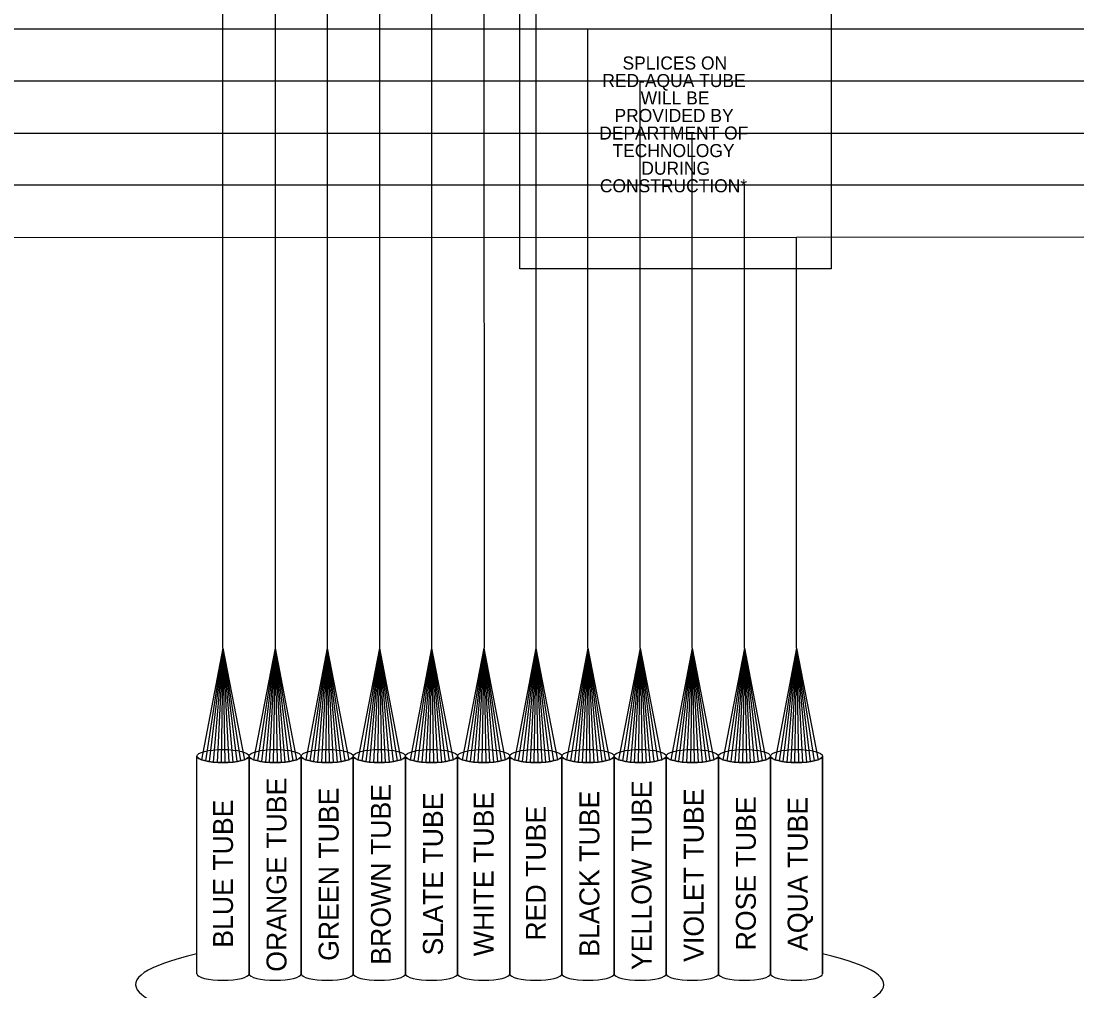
# Model space of a CAD drawing. Extents: x 1805893 to 1833564, y 708898 to 716199.
# Drawn here: x 1832449.4 to 1832571.6, y 713870.5 to 713982.1 of the extents above; entities that cross this region are included whole.
import ezdxf

# ---------------------------------------------------------------- set-up
doc = ezdxf.new("R2010")
doc.units = 0
doc.layers.add('SH_Data', color=7, linetype='Continuous')
doc.layers.add('SH_Text', color=7, linetype='Continuous')

msp = doc.modelspace()

# ---------------------------------------------------------------- linework, layer by layer
at = {"layer": 'SH_Data'}
for p, q in [((1832472.58, 713909.97), (1832472.58, 714031.78)), ((1832478.58, 714014.82), (1832478.58, 713909.97)), ((1832496.58, 714014.82), (1832496.58, 713909.97)), ((1832484.58, 714008.82), (1832484.58, 713909.97)), ((1832490.58, 714002.82), (1832490.58, 713909.97)), ((1832502.58, 714002.82), (1832502.62, 713909.97)), ((1832508.58, 713987.23), (1832508.58, 713909.97)), ((1832424.05, 713981.23), (1832514.58, 713981.23)), ((1832514.58, 713981.23), (1832571.62, 713981.23)), ((1832514.58, 713909.97), (1832514.58, 713981.23)), ((1832424.05, 713975.23), (1832520.58, 713975.23)), ((1832520.58, 713975.23), (1832571.62, 713975.23)), ((1832520.58, 713909.97), (1832520.58, 713975.23)), ((1832424.05, 713969.23), (1832526.58, 713969.23)), ((1832526.58, 713969.23), (1832571.62, 713969.23)), ((1832526.58, 713909.97), (1832526.58, 713969.23)), ((1832532.59, 713963.23), (1832424.05, 713963.23)), ((1832532.58, 713909.97), (1832532.58, 713963.23)), ((1832571.62, 713963.23), (1832532.59, 713963.23)), ((1832538.58, 713957.23), (1832424.05, 713957.19)), ((1832538.57, 713909.97), (1832538.59, 713957.23)), ((1832571.62, 713957.24), (1832538.59, 713957.23)), ((1832472.58, 713909.97), (1832470.11, 713897.12)), ((1832472.58, 713909.97), (1832470.56, 713897)), ((1832472.58, 713909.97), (1832471.01, 713896.91)), ((1832472.58, 713909.97), (1832471.46, 713896.85)), ((1832472.58, 713909.97), (1832471.91, 713896.82)), ((1832472.58, 713909.97), (1832472.36, 713896.8)), ((1832472.58, 713909.97), (1832473.71, 713896.85)), ((1832472.58, 713909.97), (1832474.16, 713896.91)), ((1832472.58, 713909.97), (1832474.61, 713897)), ((1832472.58, 713909.97), (1832475.06, 713897.12)), ((1832472.58, 713909.97), (1832473.26, 713896.82)), ((1832472.58, 713909.97), (1832472.81, 713896.8)), ((1832478.58, 713909.97), (1832476.11, 713897.12)), ((1832478.58, 713909.97), (1832476.56, 713897)), ((1832478.58, 713909.97), (1832477.01, 713896.91)), ((1832478.58, 713909.97), (1832477.46, 713896.85)), ((1832478.58, 713909.97), (1832477.91, 713896.82)), ((1832478.58, 713909.97), (1832478.36, 713896.8)), ((1832478.58, 713909.97), (1832479.71, 713896.85)), ((1832478.58, 713909.97), (1832480.16, 713896.91)), ((1832478.58, 713909.97), (1832480.61, 713897)), ((1832478.58, 713909.97), (1832481.06, 713897.12)), ((1832478.58, 713909.97), (1832479.26, 713896.82)), ((1832478.58, 713909.97), (1832478.81, 713896.8)), ((1832484.58, 713909.97), (1832482.11, 713897.12)), ((1832484.58, 713909.97), (1832482.56, 713897)), ((1832484.58, 713909.97), (1832483.01, 713896.91)), ((1832484.58, 713909.97), (1832483.46, 713896.85)), ((1832484.58, 713909.97), (1832483.91, 713896.82)), ((1832484.58, 713909.97), (1832484.36, 713896.8)), ((1832484.58, 713909.97), (1832485.71, 713896.85)), ((1832484.58, 713909.97), (1832486.16, 713896.91)), ((1832484.58, 713909.97), (1832486.61, 713897)), ((1832484.58, 713909.97), (1832487.06, 713897.12)), ((1832484.58, 713909.97), (1832485.26, 713896.82)), ((1832484.58, 713909.97), (1832484.81, 713896.8)), ((1832490.58, 713909.97), (1832488.11, 713897.12)), ((1832490.58, 713909.97), (1832488.56, 713897)), ((1832490.58, 713909.97), (1832489.01, 713896.91)), ((1832490.58, 713909.97), (1832489.46, 713896.85)), ((1832490.58, 713909.97), (1832489.91, 713896.82)), ((1832490.58, 713909.97), (1832490.36, 713896.8)), ((1832490.58, 713909.97), (1832491.71, 713896.85)), ((1832490.58, 713909.97), (1832492.16, 713896.91)), ((1832490.58, 713909.97), (1832492.61, 713897)), ((1832490.58, 713909.97), (1832493.06, 713897.12)), ((1832490.58, 713909.97), (1832491.26, 713896.82)), ((1832490.58, 713909.97), (1832490.81, 713896.8)), ((1832496.58, 713909.97), (1832494.11, 713897.12)), ((1832496.58, 713909.97), (1832494.56, 713897)), ((1832496.58, 713909.97), (1832495.01, 713896.91)), ((1832496.58, 713909.97), (1832495.46, 713896.85)), ((1832496.58, 713909.97), (1832495.91, 713896.82)), ((1832496.58, 713909.97), (1832496.36, 713896.8)), ((1832496.58, 713909.97), (1832497.71, 713896.85)), ((1832496.58, 713909.97), (1832498.16, 713896.91)), ((1832496.58, 713909.97), (1832498.61, 713897)), ((1832496.58, 713909.97), (1832499.06, 713897.12)), ((1832496.58, 713909.97), (1832497.26, 713896.82)), ((1832496.58, 713909.97), (1832496.81, 713896.8)), ((1832502.58, 713909.97), (1832500.11, 713897.12)), ((1832502.58, 713909.97), (1832500.56, 713897)), ((1832502.58, 713909.97), (1832501.01, 713896.91)), ((1832502.58, 713909.97), (1832501.46, 713896.85)), ((1832502.58, 713909.97), (1832501.91, 713896.82)), ((1832502.58, 713909.97), (1832502.36, 713896.8)), ((1832502.58, 713909.97), (1832503.71, 713896.85)), ((1832502.58, 713909.97), (1832504.16, 713896.91)), ((1832502.58, 713909.97), (1832504.61, 713897)), ((1832502.58, 713909.97), (1832505.06, 713897.12)), ((1832502.58, 713909.97), (1832503.26, 713896.82)), ((1832502.58, 713909.97), (1832502.81, 713896.8)), ((1832508.58, 713909.97), (1832506.11, 713897.12)), ((1832508.58, 713909.97), (1832506.56, 713897)), ((1832508.58, 713909.97), (1832507.01, 713896.91)), ((1832508.58, 713909.97), (1832507.46, 713896.85)), ((1832508.58, 713909.97), (1832507.91, 713896.82)), ((1832508.58, 713909.97), (1832508.36, 713896.8)), ((1832508.58, 713909.97), (1832509.71, 713896.85)), ((1832508.58, 713909.97), (1832510.16, 713896.91)), ((1832508.58, 713909.97), (1832510.61, 713897)), ((1832508.58, 713909.97), (1832511.06, 713897.12)), ((1832508.58, 713909.97), (1832509.26, 713896.82)), ((1832508.58, 713909.97), (1832508.81, 713896.8)), ((1832514.58, 713909.97), (1832512.11, 713897.12)), ((1832514.58, 713909.97), (1832512.56, 713897)), ((1832514.58, 713909.97), (1832513.01, 713896.91)), ((1832514.58, 713909.97), (1832513.46, 713896.85)), ((1832514.58, 713909.97), (1832513.91, 713896.82)), ((1832514.58, 713909.97), (1832514.36, 713896.8)), ((1832514.58, 713909.97), (1832515.71, 713896.85)), ((1832514.58, 713909.97), (1832516.16, 713896.91)), ((1832514.58, 713909.97), (1832516.61, 713897)), ((1832514.58, 713909.97), (1832517.06, 713897.12)), ((1832514.58, 713909.97), (1832515.26, 713896.82)), ((1832514.58, 713909.97), (1832514.81, 713896.8)), ((1832520.58, 713909.97), (1832518.11, 713897.12)), ((1832520.58, 713909.97), (1832518.56, 713897)), ((1832520.58, 713909.97), (1832519.01, 713896.91)), ((1832520.58, 713909.97), (1832519.46, 713896.85)), ((1832520.58, 713909.97), (1832519.91, 713896.82)), ((1832520.58, 713909.97), (1832520.36, 713896.8)), ((1832520.58, 713909.97), (1832521.71, 713896.85)), ((1832520.58, 713909.97), (1832522.16, 713896.91)), ((1832520.58, 713909.97), (1832522.61, 713897)), ((1832520.58, 713909.97), (1832523.06, 713897.12)), ((1832520.58, 713909.97), (1832521.26, 713896.82)), ((1832520.58, 713909.97), (1832520.81, 713896.8)), ((1832526.58, 713909.97), (1832524.11, 713897.12)), ((1832526.58, 713909.97), (1832524.56, 713897)), ((1832526.58, 713909.97), (1832525.01, 713896.91)), ((1832526.58, 713909.97), (1832525.46, 713896.85)), ((1832526.58, 713909.97), (1832525.91, 713896.82)), ((1832526.58, 713909.97), (1832526.36, 713896.8)), ((1832526.58, 713909.97), (1832527.71, 713896.85)), ((1832526.58, 713909.97), (1832528.16, 713896.91)), ((1832526.58, 713909.97), (1832528.61, 713897)), ((1832526.58, 713909.97), (1832529.06, 713897.12)), ((1832526.58, 713909.97), (1832527.26, 713896.82)), ((1832526.58, 713909.97), (1832526.81, 713896.8)), ((1832532.58, 713909.97), (1832530.11, 713897.12)), ((1832532.58, 713909.97), (1832530.56, 713897)), ((1832532.58, 713909.97), (1832531.01, 713896.91)), ((1832532.58, 713909.97), (1832531.46, 713896.85)), ((1832532.58, 713909.97), (1832531.91, 713896.82)), ((1832532.58, 713909.97), (1832532.36, 713896.8)), ((1832532.58, 713909.97), (1832533.71, 713896.85)), ((1832532.58, 713909.97), (1832534.16, 713896.91)), ((1832532.58, 713909.97), (1832534.61, 713897)), ((1832532.58, 713909.97), (1832535.06, 713897.12)), ((1832532.58, 713909.97), (1832533.26, 713896.82)), ((1832532.58, 713909.97), (1832532.81, 713896.8)), ((1832538.58, 713909.97), (1832536.11, 713897.12)), ((1832538.58, 713909.97), (1832536.56, 713897)), ((1832538.58, 713909.97), (1832537.01, 713896.91)), ((1832538.58, 713909.97), (1832537.46, 713896.85)), ((1832538.58, 713909.97), (1832537.91, 713896.82)), ((1832538.58, 713909.97), (1832538.36, 713896.8)), ((1832538.58, 713909.97), (1832539.71, 713896.85)), ((1832538.58, 713909.97), (1832540.16, 713896.91)), ((1832538.58, 713909.97), (1832540.61, 713897)), ((1832538.58, 713909.97), (1832541.06, 713897.12)), ((1832538.58, 713909.97), (1832539.26, 713896.82)), ((1832538.58, 713909.97), (1832538.81, 713896.8)), ((1832469.58, 713872.5), (1832469.58, 713897.55)), ((1832469.58, 713872.5), (1832469.58, 713897.55)), ((1832475.58, 713897.55), (1832475.58, 713872.5)), ((1832475.58, 713872.5), (1832475.58, 713897.55)), ((1832481.58, 713872.5), (1832481.58, 713897.55)), ((1832481.58, 713897.55), (1832481.58, 713872.5)), ((1832487.58, 713897.55), (1832487.58, 713872.5)), ((1832487.58, 713872.5), (1832487.58, 713897.55)), ((1832493.58, 713897.55), (1832493.58, 713872.5)), ((1832493.58, 713872.5), (1832493.58, 713897.55)), ((1832499.58, 713897.55), (1832499.58, 713872.5)), ((1832499.58, 713872.5), (1832499.58, 713897.55)), ((1832505.58, 713897.55), (1832505.58, 713872.5)), ((1832505.58, 713872.5), (1832505.58, 713897.55)), ((1832511.58, 713897.55), (1832511.58, 713872.5)), ((1832511.58, 713872.5), (1832511.58, 713897.55)), ((1832517.58, 713872.5), (1832517.58, 713897.55)), ((1832517.58, 713897.55), (1832517.58, 713872.5)), ((1832523.58, 713897.55), (1832523.58, 713872.5)), ((1832523.58, 713872.5), (1832523.58, 713897.55)), ((1832529.58, 713897.55), (1832529.58, 713872.5)), ((1832529.58, 713872.5), (1832529.58, 713897.55)), ((1832535.58, 713897.55), (1832535.58, 713872.5)), ((1832535.58, 713872.5), (1832535.58, 713897.55)), ((1832541.58, 713897.55), (1832541.58, 713872.5)), ((1832541.58, 713872.5), (1832541.58, 713897.55)), ((1832541.58, 713897.55), (1832541.58, 713874.78))]:
    msp.add_line(p, q, dxfattribs=at)
for centre in [(1832472.58, 713897.55), (1832478.58, 713897.55), (1832484.58, 713897.55), (1832490.58, 713897.55), (1832496.58, 713897.55), (1832502.58, 713897.55), (1832508.58, 713897.55), (1832514.58, 713897.55), (1832520.58, 713897.55), (1832526.58, 713897.55), (1832532.58, 713897.55), (1832538.58, 713897.55)]:
    msp.add_ellipse(centre, major_axis=(3, 0), ratio=0.25, dxfattribs=at)
for centre, major_axis, ratio, start_param, end_param in [((1832472.58, 713897.55), (3, 0), 0.25, 3.141593, 6.283185), ((1832478.58, 713897.55), (3, 0), 0.25, 3.141593, 6.283185), ((1832484.58, 713897.55), (3, 0), 0.25, 3.141593, 6.283185), ((1832490.58, 713897.55), (3, 0), 0.25, 3.141593, 6.283185), ((1832496.58, 713897.55), (3, 0), 0.25, 3.141593, 6.283185), ((1832502.58, 713897.55), (3, 0), 0.25, 3.141593, 6.283185), ((1832508.58, 713897.55), (3, 0), 0.25, 3.141593, 6.283185), ((1832514.58, 713897.55), (3, 0), 0.25, 3.141593, 6.283185), ((1832520.58, 713897.55), (3, 0), 0.25, 3.141593, 6.283185), ((1832526.58, 713897.55), (3, 0), 0.25, 3.141593, 6.283185), ((1832532.58, 713897.55), (3, 0), 0.25, 3.141593, 6.283185), ((1832538.58, 713897.55), (3, 0), 0.25, 3.141593, 6.283185), ((1832505.58, 713871.25), (43.05, 0), 0.149566, 2.561295, 6.863483), ((1832505.58, 713871.25), (43.05, 0), 0.149566, 2.561295, 6.863483), ((1832472.58, 713872.5), (3, 0), 0.25, 3.141593, 6.283185), ((1832472.58, 713872.5), (3, 0), 0.25, 3.141593, 6.283185), ((1832478.58, 713872.5), (3, 0), 0.25, 3.141593, 6.283185), ((1832478.58, 713872.5), (3, 0), 0.25, 3.141593, 6.283185), ((1832484.58, 713872.5), (3, 0), 0.25, 3.141593, 6.283185), ((1832484.58, 713872.5), (3, 0), 0.25, 3.141593, 6.283185), ((1832490.58, 713872.5), (3, 0), 0.25, 3.141593, 6.283185), ((1832490.58, 713872.5), (3, 0), 0.25, 3.141593, 6.283185), ((1832496.58, 713872.5), (3, 0), 0.25, 3.141593, 6.283185), ((1832496.58, 713872.5), (3, 0), 0.25, 3.141593, 6.283185), ((1832502.58, 713872.5), (3, 0), 0.25, 3.141593, 6.283185), ((1832502.58, 713872.5), (3, 0), 0.25, 3.141593, 6.283185), ((1832508.58, 713872.5), (3, 0), 0.25, 3.141593, 6.283185), ((1832508.58, 713872.5), (3, 0), 0.25, 3.141593, 6.283185), ((1832514.58, 713872.5), (3, 0), 0.25, 3.141593, 6.283185), ((1832514.58, 713872.5), (3, 0), 0.25, 3.141593, 6.283185), ((1832520.58, 713872.5), (3, 0), 0.25, 3.141593, 6.283185), ((1832520.58, 713872.5), (3, 0), 0.25, 3.141593, 6.283185), ((1832526.58, 713872.5), (3, 0), 0.25, 3.141593, 6.283185), ((1832526.58, 713872.5), (3, 0), 0.25, 3.141593, 6.283185), ((1832532.58, 713872.5), (3, 0), 0.25, 3.141593, 6.283185), ((1832532.58, 713872.5), (3, 0), 0.25, 3.141593, 6.283185), ((1832538.58, 713872.5), (3, 0), 0.25, 3.141593, 6.283185), ((1832538.58, 713872.5), (3, 0), 0.25, 3.141593, 6.283185)]:
    msp.add_ellipse(centre, major_axis=major_axis, ratio=ratio, start_param=start_param, end_param=end_param, dxfattribs=at)
at = {"layer": 'SH_Text'}
msp.add_lwpolyline([(1832506.75, 713988.86), (1832542.57, 713988.86), (1832542.57, 713953.61), (1832506.75, 713953.61)], close=True, dxfattribs=at)

# ---------------------------------------------------------------- texts
at = {"layer": 'SH_Data'}
for s, height, p in [('ORANGE TUBE', 2.2947, (1832479.89, 713872.73)), ('YELLOW TUBE', 2.2947, (1832521.89, 713872.92)), ('GREEN TUBE', 2.295, (1832485.89, 713873.98)), ('BROWN TUBE', 2.295, (1832491.89, 713873.54)), ('SLATE TUBE', 2.295, (1832497.89, 713874.6)), ('WHITE TUBE', 2.295, (1832503.73, 713874.52)), ('BLACK TUBE', 2.295, (1832515.89, 713874.46)), ('VIOLET TUBE', 2.2947, (1832527.89, 713873.87)), ('BLUE TUBE', 2.295, (1832473.73, 713875.49)), ('ROSE TUBE', 2.295, (1832533.89, 713875.19)), ('AQUA TUBE', 2.295, (1832539.85, 713875.12)), ('RED TUBE', 2.295, (1832509.73, 713876.31))]:
    msp.add_text(s, height=height, rotation=90, dxfattribs=at).set_placement(p)
at = {"layer": 'SH_Text'}
for s, p in [('SPLICES ON ', (1832518.55, 713976.55)), ('RED-AQUA TUBE ', (1832516.23, 713974.53)), ('WILL BE ', (1832520.64, 713972.53)), ('PROVIDED BY ', (1832517.63, 713970.51)), ('DEPARTMENT OF ', (1832515.87, 713968.49)), ('TECHNOLOGY ', (1832517.4, 713966.47)), ('DURING ', (1832520.72, 713964.44)), ('CONSTRUCTION*', (1832515.95, 713962.42))]:
    msp.add_text(s, height=1.5, rotation=360, dxfattribs=at).set_placement(p)

doc.saveas('drawing.dxf')
